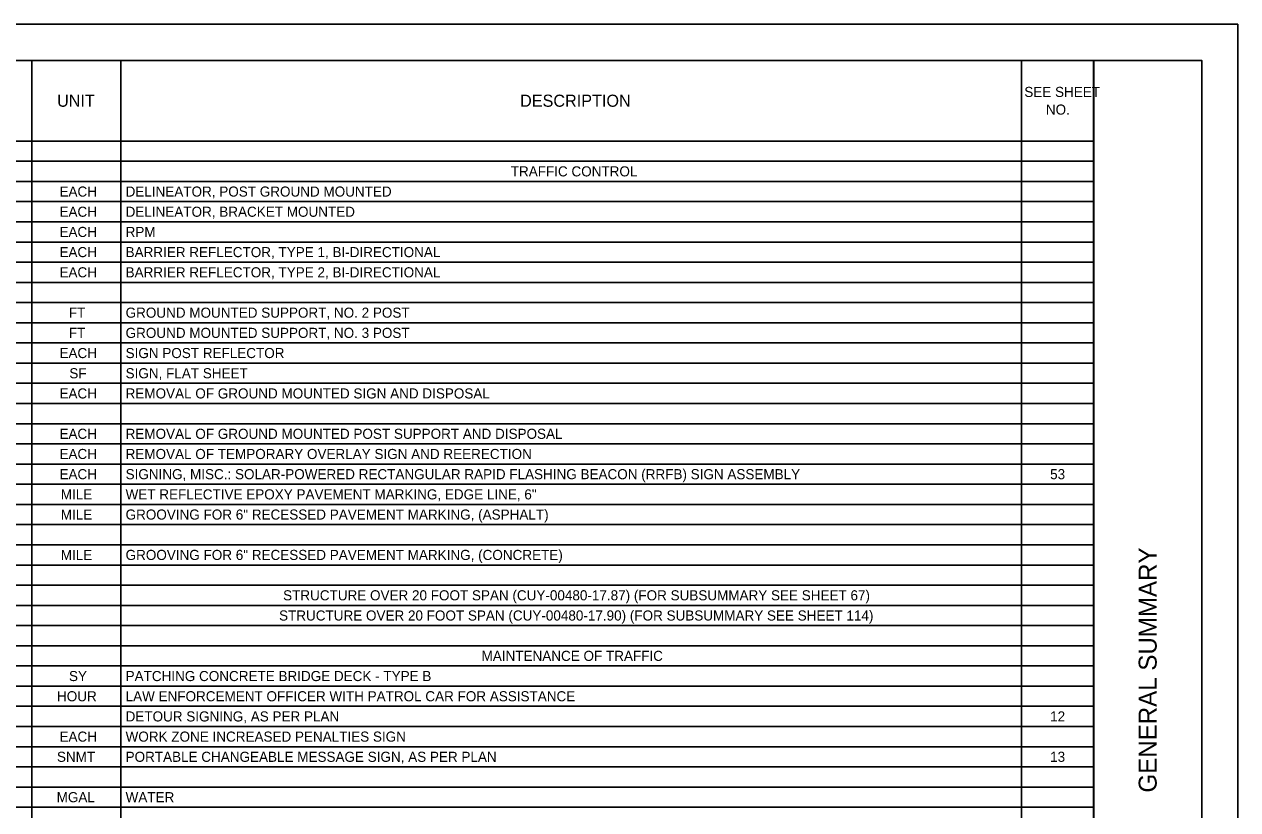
# Model space of a CAD drawing. Extents: x 0 to 34, y 0 to 22.
# Drawn here: x 17.16 to 34, y 11.11 to 22 of the extents above; entities that cross this region are included whole.
import ezdxf

# ---------------------------------------------------------------- set-up
doc = ezdxf.new("R2010")
doc.units = 0
for name, color, linetype in [('SH_Border', 7, 'Continuous'), ('SH_Cut_Line', 7, 'Continuous'), ('SH_Data', 7, 'Continuous'), ('SH_Text', 7, 'Continuous')]:
    doc.layers.add(name, color=color, linetype=linetype)

msp = doc.modelspace()

# ---------------------------------------------------------------- linework, layer by layer
at = {"layer": 'SH_Border'}
msp.add_line((32, 0.5), (32, 21.5), dxfattribs=at)
msp.add_lwpolyline([(1.5, 21.5), (33.5, 21.5), (33.5, 0.5), (1.5, 0.5)], close=True, dxfattribs=at)
at = {"layer": 'SH_Cut_Line'}
msp.add_lwpolyline([(0, 0), (34, 0), (34, 22), (0, 22)], close=True, dxfattribs=at)
at = {"layer": 'SH_Data'}
for p, q in [((1.5, 21.5), (32.004, 21.5)), ((17.262, 21.5), (17.262, 0.5)), ((18.498, 21.5), (18.498, 0.5)), ((30.999, 21.5), (30.999, 0.5)), ((32.004, 21.5), (32.004, 0.5)), ((1.5, 20.38), (32.004, 20.38)), ((1.5, 20.1), (32.004, 20.1)), ((1.5, 19.82), (32.004, 19.82)), ((1.5, 19.54), (32.004, 19.54)), ((1.5, 19.26), (32.004, 19.26)), ((1.5, 18.98), (32.004, 18.98)), ((1.5, 18.7), (32.004, 18.7)), ((1.5, 18.42), (32.004, 18.42)), ((1.5, 18.14), (32.004, 18.14)), ((1.5, 17.86), (32.004, 17.86)), ((1.5, 17.58), (32.004, 17.58)), ((1.5, 17.3), (32.004, 17.3)), ((1.5, 17.02), (32.004, 17.02)), ((1.5, 16.74), (32.004, 16.74)), ((1.5, 16.46), (32.004, 16.46)), ((1.5, 16.18), (32.004, 16.18)), ((1.5, 15.9), (32.004, 15.9)), ((1.5, 15.62), (32.004, 15.62)), ((1.5, 15.34), (32.004, 15.34)), ((1.5, 15.06), (32.004, 15.06)), ((1.5, 14.78), (32.004, 14.78)), ((1.5, 14.5), (32.004, 14.5)), ((1.5, 14.22), (32.004, 14.22)), ((1.5, 13.94), (32.004, 13.94)), ((1.5, 13.66), (32.004, 13.66)), ((1.5, 13.38), (32.004, 13.38)), ((1.5, 13.1), (32.004, 13.1)), ((1.5, 12.82), (32.004, 12.82)), ((1.5, 12.54), (32.004, 12.54)), ((1.5, 12.26), (32.004, 12.26)), ((1.5, 11.98), (32.004, 11.98)), ((1.5, 11.7), (32.004, 11.7)), ((1.5, 11.42), (32.004, 11.42)), ((1.5, 11.14), (32.004, 11.14))]:
    msp.add_line(p, q, dxfattribs=at)

# ---------------------------------------------------------------- texts
msp.add_text('GENERAL SUMMARY', height=0.25, rotation=90, dxfattribs=at).set_placement((32.875, 11.344))
at = {"layer": 'SH_Text'}
for s, height, p in [('SEE SHEET ', 0.14, (31.038, 20.992)), ('UNIT', 0.168, (17.613, 20.856)), ('DESCRIPTION', 0.168, (24.039, 20.856)), ('NO.', 0.14, (31.337, 20.747)), ('TRAFFIC CONTROL', 0.14, (23.91, 19.89)), ('EACH', 0.14, (17.646, 19.61)), ('DELINEATOR, POST GROUND MOUNTED', 0.14, (18.564, 19.61)), ('EACH', 0.14, (17.646, 19.33)), ('DELINEATOR, BRACKET MOUNTED', 0.14, (18.564, 19.33)), ('EACH', 0.14, (17.646, 19.05)), ('RPM', 0.14, (18.564, 19.05)), ('EACH', 0.14, (17.646, 18.77)), ('BARRIER REFLECTOR, TYPE 1, BI-DIRECTIONAL', 0.14, (18.564, 18.77)), ('EACH', 0.14, (17.646, 18.49)), ('BARRIER REFLECTOR, TYPE 2, BI-DIRECTIONAL', 0.14, (18.564, 18.49)), ('FT', 0.14, (17.776, 17.93)), ('GROUND MOUNTED SUPPORT, NO. 2 POST', 0.14, (18.564, 17.93)), ('FT', 0.14, (17.776, 17.65)), ('GROUND MOUNTED SUPPORT, NO. 3 POST', 0.14, (18.564, 17.65)), ('EACH', 0.14, (17.646, 17.37)), ('SIGN POST REFLECTOR', 0.14, (18.564, 17.37)), ('SF', 0.14, (17.783, 17.09)), ('SIGN, FLAT SHEET', 0.14, (18.564, 17.09)), ('EACH', 0.14, (17.646, 16.81)), ('REMOVAL OF GROUND MOUNTED SIGN AND DISPOSAL', 0.14, (18.564, 16.81)), ('EACH', 0.14, (17.646, 16.25)), ('REMOVAL OF GROUND MOUNTED POST SUPPORT AND DISPOSAL', 0.14, (18.564, 16.25)), ('EACH', 0.14, (17.646, 15.97)), ('REMOVAL OF TEMPORARY OVERLAY SIGN AND REERECTION', 0.14, (18.564, 15.97)), ('EACH', 0.14, (17.646, 15.69)), ('SIGNING, MISC.: SOLAR-POWERED RECTANGULAR RAPID FLASHING BEACON (RRFB) SIGN ASSEMBLY', 0.14, (18.564, 15.69)), ('53', 0.14, (31.396, 15.69)), ('MILE', 0.14, (17.664, 15.41)), ('WET REFLECTIVE EPOXY PAVEMENT MARKING, EDGE LINE, 6"', 0.14, (18.564, 15.41)), ('MILE', 0.14, (17.664, 15.13)), ('GROOVING FOR 6" RECESSED PAVEMENT MARKING, (ASPHALT)', 0.14, (18.564, 15.13)), ('MILE', 0.14, (17.664, 14.57)), ('GROOVING FOR 6" RECESSED PAVEMENT MARKING, (CONCRETE)', 0.14, (18.564, 14.57)), ('STRUCTURE OVER 20 FOOT SPAN (CUY-00480-17.87) (FOR SUBSUMMARY SEE SHEET 67)', 0.14, (20.75, 14.01)), ('STRUCTURE OVER 20 FOOT SPAN (CUY-00480-17.90) (FOR SUBSUMMARY SEE SHEET 114)', 0.14, (20.694, 13.73)), ('MAINTENANCE OF TRAFFIC', 0.14, (23.505, 13.17)), ('SY', 0.14, (17.778, 12.89)), ('PATCHING CONCRETE BRIDGE DECK - TYPE B', 0.14, (18.564, 12.89)), ('HOUR', 0.14, (17.612, 12.61)), ('LAW ENFORCEMENT OFFICER WITH PATROL CAR FOR ASSISTANCE', 0.14, (18.564, 12.61)), ('DETOUR SIGNING, AS PER PLAN', 0.14, (18.564, 12.33)), ('12', 0.14, (31.396, 12.33)), ('EACH', 0.14, (17.646, 12.05)), ('WORK ZONE INCREASED PENALTIES SIGN', 0.14, (18.564, 12.05)), ('SNMT', 0.14, (17.611, 11.77)), ('PORTABLE CHANGEABLE MESSAGE SIGN, AS PER PLAN', 0.14, (18.564, 11.77)), ('13', 0.14, (31.396, 11.77)), ('MGAL', 0.14, (17.607, 11.21)), ('WATER', 0.14, (18.564, 11.21))]:
    msp.add_text(s, height=height, dxfattribs=at).set_placement(p)

doc.saveas('drawing.dxf')
